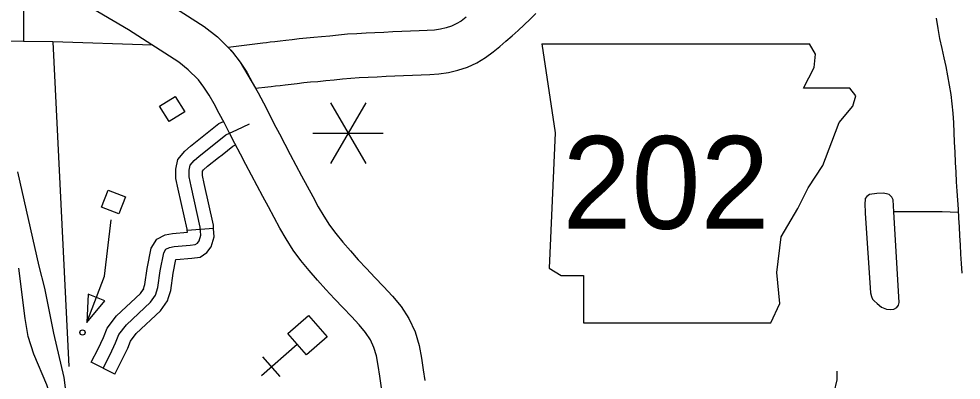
# Model space of a CAD drawing. Extents: x 1370130 to 1380143, y 377636 to 380256.
# Drawn here: x 1377248.1 to 1377398.1, y 379127.4 to 379185.1 of the extents above; entities that cross this region are included whole.
import ezdxf

# ---------------------------------------------------------------- set-up
doc = ezdxf.new("R2010")
doc.units = 0
for name, color, linetype in [('Level 10', 7, 'Continuous'), ('Level 15', 7, 'Continuous'), ('Level 21', 7, 'Continuous'), ('Level 33', 7, 'Continuous'), ('Level 35', 7, 'Continuous'), ('Level 4', 7, 'Continuous'), ('Level 45', 7, 'Continuous'), ('Level 48', 7, 'Continuous'), ('Level 5', 7, 'Continuous'), ('Level 56', 7, 'Continuous'), ('Level 57', 7, 'Continuous')]:
    doc.layers.add(name, color=color, linetype=linetype)

msp = doc.modelspace()

# ---------------------------------------------------------------- linework, layer by layer
at = {"layer": 'Level 10'}
for points in [[(1377319.32, 379185.31), (1377318.51, 379184.7), (1377317.75, 379184.25), (1377316.98, 379183.89), (1377316.15, 379183.61), (1377315.26, 379183.42), (1377314.27, 379183.28), (1377313.14, 379183.2), (1377311.86, 379183.14), (1377310.48, 379183.09), (1377309.07, 379183.03), (1377307.65, 379182.97), (1377306.23, 379182.9), (1377304.81, 379182.83), (1377303.4, 379182.76), (1377301.94, 379182.69), (1377300.44, 379182.6), (1377298.98, 379182.46), (1377297.61, 379182.32), (1377296.32, 379182.19), (1377295.09, 379182.07), (1377293.91, 379181.97), (1377292.76, 379181.86), (1377291.65, 379181.74), (1377290.63, 379181.62), (1377289.71, 379181.51), (1377288.87, 379181.41), (1377288.13, 379181.32), (1377287.54, 379181.24), (1377286.98, 379181.19), (1377281.42, 379180.52), (1377282.14, 379179.76), (1377283.33, 379178.18), (1377285.81, 379174)], [(1377285.81, 379174), (1377287.73, 379174.23), (1377288.3, 379174.29), (1377288.99, 379174.37), (1377289.72, 379174.46), (1377290.53, 379174.56), (1377291.45, 379174.67), (1377292.43, 379174.78), (1377293.46, 379174.89), (1377294.55, 379175), (1377295.74, 379175.1), (1377297.01, 379175.22), (1377298.33, 379175.36), (1377299.66, 379175.5), (1377300.98, 379175.62), (1377302.31, 379175.7), (1377303.73, 379175.76), (1377305.17, 379175.84), (1377306.58, 379175.91), (1377307.97, 379175.98), (1377309.37, 379176.04), (1377310.76, 379176.1), (1377312.14, 379176.15), (1377313.54, 379176.21), (1377315, 379176.31), (1377316.5, 379176.52), (1377318.02, 379176.86), (1377319.55, 379177.37), (1377321.04, 379178.05), (1377322.43, 379178.9), (1377323.63, 379179.8), (1377324.68, 379180.65), (1377325.66, 379181.48), (1377326.64, 379182.34), (1377327.62, 379183.22), (1377328.57, 379184.12), (1377329.51, 379185.03), (1377330.44, 379185.94)], [(1377394.17, 379185.2), (1377394.41, 379183.54), (1377394.7, 379181.92), (1377395.05, 379180.34), (1377395.4, 379178.87), (1377395.7, 379177.45), (1377395.98, 379175.97), (1377396.24, 379174.47), (1377396.47, 379172.98), (1377396.67, 379171.5), (1377396.81, 379170.02), (1377396.91, 379168.5), (1377396.99, 379166.95), (1377397.05, 379165.38), (1377397.11, 379163.78), (1377397.18, 379162.17), (1377397.28, 379160.6), (1377397.37, 379159.09), (1377397.46, 379157.6), (1377397.55, 379156.14), (1377397.64, 379154.69), (1377397.73, 379153.28), (1377397.81, 379151.87), (1377397.88, 379150.46), (1377397.96, 379149.03), (1377398.04, 379147.55), (1377398.14, 379146.05), (1377398.22, 379144.53)]]:
    msp.add_lwpolyline(points, dxfattribs=at)
at = {"layer": 'Level 15'}
for points in [[(1377246.98, 379202.62), (1377248.18, 379201.74), (1377249.65, 379200.84), (1377269.25, 379189.28), (1377277.62, 379183.86), (1377279.73, 379182.22), (1377281.87, 379180.07)], [(1377276.66, 379175.4), (1377275.09, 379176.96), (1377273.56, 379178.15), (1377265.57, 379183.32), (1377246.06, 379194.84)], [(1377281.87, 379180.07), (1377282.14, 379179.76), (1377283.33, 379178.18), (1377284.39, 379176.54), (1377285.32, 379174.88), (1377286.19, 379173.28), (1377287.04, 379171.66), (1377287.89, 379170.02), (1377288.73, 379168.39), (1377289.59, 379166.74), (1377290.46, 379165.08), (1377291.33, 379163.41), (1377292.22, 379161.72), (1377293.12, 379160.04), (1377294.01, 379158.37), (1377294.9, 379156.72), (1377295.78, 379155.11), (1377296.65, 379153.58), (1377297.56, 379152.17), (1377298.56, 379150.81), (1377299.67, 379149.44), (1377300.89, 379148.05), (1377302.16, 379146.64), (1377303.47, 379145.23), (1377304.81, 379143.82), (1377306.19, 379142.38), (1377307.58, 379140.86), (1377308.96, 379139.18), (1377310.22, 379137.26), (1377311.2, 379135.14), (1377311.84, 379132.99), (1377312.23, 379130.96), (1377312.51, 379129.09), (1377312.76, 379127.39)], [(1377305.85, 379126.22), (1377305.59, 379128.07), (1377305.33, 379129.78), (1377305.03, 379131.31), (1377304.63, 379132.66), (1377304.08, 379133.86), (1377303.31, 379135.03), (1377302.29, 379136.27), (1377301.08, 379137.59), (1377299.75, 379138.99), (1377298.37, 379140.43), (1377296.99, 379141.91), (1377295.65, 379143.4), (1377294.33, 379144.92), (1377293.03, 379146.51), (1377291.79, 379148.2), (1377290.66, 379149.96), (1377289.67, 379151.69), (1377288.75, 379153.37), (1377287.84, 379155.06), (1377286.94, 379156.75), (1377286.04, 379158.45), (1377285.14, 379160.15), (1377284.25, 379161.83), (1377283.38, 379163.51), (1377282.52, 379165.17), (1377281.67, 379166.81), (1377280.84, 379168.41), (1377280.01, 379169.98), (1377279.19, 379171.5), (1377278.4, 379172.91), (1377277.58, 379174.18), (1377276.72, 379175.33), (1377276.66, 379175.4)]]:
    msp.add_lwpolyline(points, dxfattribs=at)
at = {"layer": 'Level 21'}
for p, q in [((1377331.37, 379181.09), (1377333.5, 379166.88)), ((1377374.95, 379179.44), (1377373.97, 379181.07)), ((1377374.71, 379177.31), (1377374.95, 379179.44)), ((1377373.06, 379173.99), (1377374.71, 379177.31)), ((1377380.4, 379173.99), (1377373.06, 379173.99)), ((1377381.35, 379172.81), (1377380.4, 379173.99)), ((1377380.87, 379171.15), (1377381.35, 379172.81)), ((1377378.74, 379168.54), (1377380.87, 379171.15)), ((1377377.56, 379165.46), (1377378.74, 379168.54)), ((1377333.5, 379166.88), (1377332.55, 379145.33)), ((1377376.13, 379161.67), (1377377.56, 379165.46)), ((1377373.77, 379158.12), (1377376.13, 379161.67)), ((1377372.11, 379154.8), (1377373.77, 379158.12)), ((1377369.5, 379150.3), (1377372.11, 379154.8)), ((1377368.79, 379144.62), (1377369.5, 379150.3)), ((1377332.55, 379145.33), (1377334.45, 379144.15)), ((1377334.45, 379144.15), (1377338, 379144.15)), ((1377338, 379144.15), (1377338, 379136.57)), ((1377369.27, 379139.65), (1377368.79, 379144.62)), ((1377367.85, 379136.57), (1377369.27, 379139.65)), ((1377338, 379136.57), (1377367.85, 379136.57))]:
    msp.add_line(p, q, dxfattribs=at)
msp.add_lwpolyline([(1377331.37, 379181.09), (1377373.97, 379181.07)], dxfattribs=at)
at = {"layer": 'Level 33'}
for points in [[(1377387.43, 379154.27), (1377387.32, 379156.2), (1377387.1, 379156.65), (1377386.68, 379157.03), (1377386.27, 379157.15), (1377385.72, 379157.24), (1377384.72, 379157.19), (1377383.55, 379157.03), (1377383.13, 379156.73), (1377382.88, 379156.44), (1377382.84, 379156.15), (1377382.8, 379155.65), (1377382.84, 379154.1), (1377383.72, 379141.39), (1377383.87, 379140.8), (1377384.05, 379140.38), (1377384.3, 379140.1), (1377384.76, 379139.67), (1377385.47, 379139.09), (1377386.23, 379138.79), (1377386.81, 379138.71), (1377387.44, 379138.79), (1377387.9, 379139.04), (1377388.15, 379139.38), (1377388.23, 379139.59), (1377388.28, 379139.84), (1377387.43, 379154.27)], [(1377397.68, 379154.17), (1377395.13, 379154.31), (1377387.43, 379154.27)]]:
    msp.add_lwpolyline(points, dxfattribs=at)
at = {"layer": 'Level 35'}
for points in [[(1377243.98, 379045.82), (1377249.38, 379053.46), (1377250.74, 379055.79), (1377253.68, 379061.74), (1377255.43, 379065.79), (1377256.65, 379069.3), (1377258.08, 379074.6), (1377258.38, 379077.98), (1377258.47, 379080.39), (1377258.3, 379084.65), (1377258.07, 379087.88), (1377257.36, 379093.36), (1377257, 379100.03), (1377256.92, 379104.1), (1377256.3, 379113.8), (1377255.85, 379123.69), (1377255.31, 379127.86), (1377253.68, 379134.93), (1377252.24, 379142.14), (1377251.33, 379145.6), (1377247.93, 379160.68)], [(1377246.23, 379052.61), (1377250.23, 379060.1), (1377255.44, 379072.05), (1377256.1, 379076.67), (1377254.45, 379086), (1377254.34, 379090.38), (1377254.74, 379096.65), (1377254.5, 379105.65), (1377254.76, 379112.39), (1377254.58, 379118.28), (1377254.31, 379120.74), (1377253.96, 379122.67), (1377252.59, 379126.68), (1377250.52, 379131.61), (1377249.59, 379134.42), (1377249.11, 379137.3), (1377248.1, 379145.33)], [(1377378.37, 379128.9), (1377378.37, 379127.5), (1377377.85, 379125.47), (1377377.64, 379123.69), (1377377.69, 379122.69), (1377378.1, 379120.42), (1377379.07, 379117.97), (1377381.76, 379112.75), (1377383.92, 379110.36), (1377388.16, 379106.38), (1377388.9, 379105.83), (1377392.33, 379104.14), (1377393.7, 379103.24), (1377396.42, 379100.63), (1377402.09, 379092.84), (1377405.07, 379088.35), (1377409.75, 379080.65), (1377411.22, 379077.37), (1377412.22, 379075.62), (1377414.67, 379072.47), (1377416.59, 379070.41), (1377418.74, 379068.55), (1377420.95, 379067.3), (1377421.19, 379067.21)]]:
    msp.add_lwpolyline(points, dxfattribs=at)
at = {"layer": 'Level 4'}
msp.add_lwpolyline([(1377269.4, 379180.85), (1377253.53, 379181.38), (1377248.83, 379181.45), (1377235.76, 379181.64)], dxfattribs=at)
at = {"layer": 'Level 45'}
for p, q in [((1377279.12, 379151.62), (1377274.93, 379151.31)), ((1377263.39, 379128.39), (1377259.65, 379130.3))]:
    msp.add_line(p, q, dxfattribs=at)
for points in [[(1377261.52, 379129.34), (1377262.64, 379131.54), (1377263.52, 379133.4), (1377264.04, 379134.71), (1377265.25, 379136.29), (1377269.07, 379139.89), (1377269.86, 379141.01), (1377270.24, 379142.22), (1377270.61, 379144.88), (1377271.17, 379147.73), (1377271.54, 379148.33), (1377272.1, 379148.61), (1377272.85, 379148.75), (1377275.41, 379148.98), (1377276.21, 379149.08), (1377276.53, 379149.31), (1377276.81, 379149.68), (1377277.09, 379150.57), (1377277, 379151.83), (1377275.55, 379158.36), (1377275.23, 379159.86), (1377275.23, 379160.93), (1377275.37, 379161.72), (1377276.02, 379162.47), (1377276.81, 379163.17), (1377279.14, 379165.03), (1377281.06, 379166.57), (1377282.83, 379167.37), (1377284.82, 379168.34)], [(1377277.28, 379166.23), (1377277.83, 379166.67), (1377279.95, 379168.38), (1377280.69, 379168.71)], [(1377274.93, 379151.31), (1377274.92, 379151.52), (1377273.5, 379157.91), (1377273.13, 379159.63), (1377273.13, 379161.11), (1377273.4, 379162.66), (1377274.53, 379163.95), (1377275.46, 379164.78), (1377277.28, 379166.23)], [(1377279.9, 379162.95), (1377280.46, 379163.4), (1377282.16, 379164.77), (1377282.62, 379164.97)], [(1377279.12, 379151.62), (1377279.08, 379152.14), (1377277.6, 379158.81), (1377277.33, 379160.08), (1377277.33, 379160.74), (1377277.33, 379160.78), (1377277.51, 379160.98), (1377278.16, 379161.56), (1377279.9, 379162.95)], [(1377271.94, 379140.62), (1377272.29, 379141.76), (1377272.68, 379144.53), (1377273.1, 379146.66), (1377273.14, 379146.67), (1377275.63, 379146.9), (1377276.99, 379147.06), (1377278.02, 379147.79), (1377278.71, 379148.71), (1377279.22, 379150.32), (1377279.12, 379151.62)], [(1377267.93, 379141.85), (1377268.18, 379142.68), (1377268.54, 379145.23), (1377269.18, 379148.5), (1377270.07, 379149.94), (1377271.43, 379150.62), (1377272.56, 379150.83), (1377274.95, 379151.05), (1377274.93, 379151.31)], [(1377259.65, 379130.3), (1377260.75, 379132.46), (1377261.59, 379134.24), (1377262.19, 379135.75), (1377263.68, 379137.71), (1377267.48, 379141.27), (1377267.96, 379141.95), (1377267.93, 379141.85)], [(1377263.39, 379128.39), (1377264.52, 379130.61), (1377265.45, 379132.57), (1377265.88, 379133.67), (1377266.81, 379134.88), (1377270.66, 379138.5), (1377271.77, 379140.07), (1377271.94, 379140.62)]]:
    msp.add_lwpolyline(points, dxfattribs=at)
at = {"layer": 'Level 48'}
for p, q in [((1377303.34, 379171.69), (1377297.74, 379161.99)), ((1377297.74, 379171.69), (1377303.34, 379161.99)), ((1377294.94, 379166.84), (1377306.14, 379166.84))]:
    msp.add_line(p, q, dxfattribs=at)
at = {"layer": 'Level 5'}
for points in [[(1377248.86, 379193.19), (1377248.83, 379181.45)], [(1377253.53, 379181.38), (1377256.07, 379129.62)]]:
    msp.add_lwpolyline(points, dxfattribs=at)
at = {"layer": 'Level 56'}
for points in [[(1377274.52, 379170.21), (1377272.04, 379168.67), (1377270.5, 379171.16), (1377272.98, 379172.69)], [(1377265.07, 379156.68), (1377264.01, 379153.96), (1377261.28, 379155.02), (1377262.34, 379157.74)], [(1377261.82, 379140.12), (1377259.15, 379141.14), (1377258.96, 379136.63)]]:
    msp.add_lwpolyline(points, close=True, dxfattribs=at)
msp.add_lwpolyline([(1377258.96, 379136.63), (1377261.77, 379144.02), (1377262.83, 379152.99)], dxfattribs=at)
msp.add_circle((1377258.25, 379135.04), 0.42, dxfattribs=at)
at = {"layer": 'Level 57'}
for p, q in [((1377286.77, 379128.21), (1377292.43, 379133.19)), ((1377289.73, 379128.02), (1377286.96, 379131.17))]:
    msp.add_line(p, q, dxfattribs=at)
msp.add_lwpolyline([(1377297.21, 379134.37), (1377293.93, 379131.48), (1377290.93, 379134.88), (1377294.21, 379137.77)], close=True, dxfattribs=at)

# ---------------------------------------------------------------- texts
at = {"layer": 'Level 21'}
msp.add_text('202', height=14.784, dxfattribs=at).set_placement((1377334.65, 379151.58))

doc.saveas('drawing.dxf')
